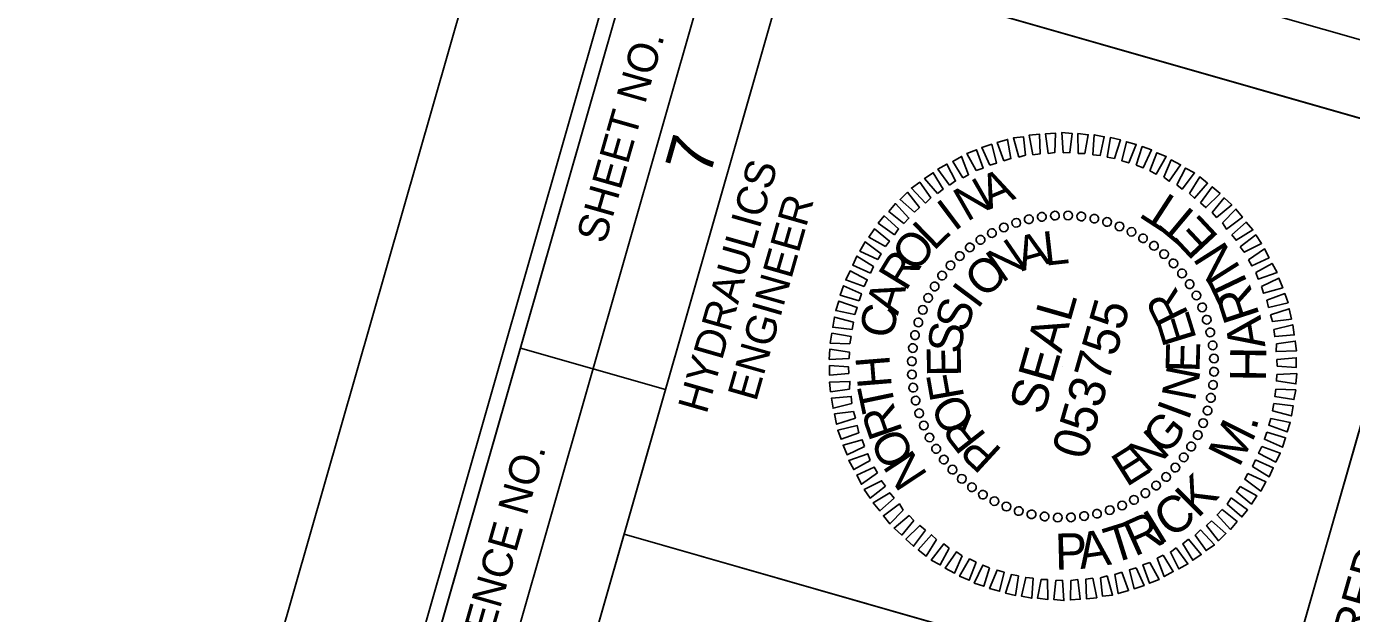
# Model space of a CAD drawing. Extents: x 2096988 to 2098509, y 687711 to 689775.
# Drawn here: x 2097368.1 to 2097587.9, y 689492.9 to 689590.3 of the extents above; entities that cross this region are included whole.
import ezdxf

# ---------------------------------------------------------------- set-up
doc = ezdxf.new("R2010")
doc.units = 0
for name, color, linetype in [('Sheet Data Field CELL', 7, 'Continuous'), ('Sheet PE Seal Cell', 7, 'Continuous'), ('Sheet Plot Border Inside CELL', 7, 'Continuous'), ('Sheet Plot Border Outside CELL', 7, 'Continuous'), ('Sheet Profile CELL', 7, 'Continuous'), ('Sheet Sticker Exception Certification CELL', 7, 'Continuous')]:
    doc.layers.add(name, color=color, linetype=linetype)

msp = doc.modelspace()

# ---------------------------------------------------------------- linework, layer by layer
at = {"layer": 'Sheet PE Seal Cell'}
for p, q in [((2097532.21, 689557.77), (2097532.21, 689557.77)), ((2097534.36, 689558.35), (2097534.36, 689558.35)), ((2097536.51, 689558.78), (2097536.51, 689558.78)), ((2097538.65, 689558.99), (2097538.65, 689558.99)), ((2097540.83, 689558.99), (2097540.83, 689558.99)), ((2097543.06, 689558.77), (2097543.06, 689558.77)), ((2097545.21, 689558.47), (2097545.21, 689558.47)), ((2097547.34, 689557.91), (2097547.34, 689557.91)), ((2097549.41, 689557.16), (2097549.41, 689557.16)), ((2097526.32, 689554.98), (2097526.32, 689554.98)), ((2097528.19, 689556.06), (2097528.19, 689556.06)), ((2097530.19, 689557.05), (2097530.19, 689557.05)), ((2097551.38, 689556.23), (2097551.38, 689556.23)), ((2097553.28, 689555.22), (2097553.28, 689555.22)), ((2097524.54, 689553.67), (2097524.54, 689553.67)), ((2097555.1, 689553.97), (2097555.1, 689553.97)), ((2097521.34, 689550.69), (2097521.34, 689550.69)), ((2097522.84, 689552.29), (2097522.84, 689552.29)), ((2097556.78, 689552.56), (2097556.78, 689552.56)), ((2097558.38, 689551.06), (2097558.38, 689551.06)), ((2097519.93, 689549.01), (2097519.93, 689549.01)), ((2097559.76, 689549.36), (2097559.76, 689549.36)), ((2097518.68, 689547.19), (2097518.68, 689547.19)), ((2097561.07, 689547.58), (2097561.07, 689547.58)), ((2097517.67, 689545.29), (2097517.67, 689545.29)), ((2097562.15, 689545.71), (2097562.15, 689545.71)), ((2097516.74, 689543.32), (2097516.74, 689543.32)), ((2097563.14, 689543.71), (2097563.14, 689543.71)), ((2097563.86, 689541.69), (2097563.86, 689541.69)), ((2097515.99, 689541.25), (2097515.99, 689541.25)), ((2097564.44, 689539.55), (2097564.44, 689539.55)), ((2097515.43, 689539.12), (2097515.43, 689539.12)), ((2097564.87, 689537.4), (2097564.87, 689537.4)), ((2097515.13, 689536.97), (2097515.13, 689536.97)), ((2097565.09, 689535.25), (2097565.09, 689535.25)), ((2097514.91, 689534.74), (2097514.91, 689534.74)), ((2097540, 689533.91), (2097540, 689533.91)), ((2097565.08, 689533.07), (2097565.08, 689533.07)), ((2097514.91, 689532.56), (2097514.91, 689532.56)), ((2097564.86, 689530.84), (2097564.86, 689530.84)), ((2097515.13, 689530.42), (2097515.13, 689530.42)), ((2097564.56, 689528.69), (2097564.56, 689528.69)), ((2097515.55, 689528.27), (2097515.55, 689528.27)), ((2097564, 689526.57), (2097564, 689526.57)), ((2097516.13, 689526.12), (2097516.13, 689526.12)), ((2097516.85, 689524.1), (2097516.85, 689524.1)), ((2097563.25, 689524.49), (2097563.25, 689524.49)), ((2097517.84, 689522.1), (2097517.84, 689522.1)), ((2097562.33, 689522.52), (2097562.33, 689522.52)), ((2097518.92, 689520.23), (2097518.92, 689520.23)), ((2097561.31, 689520.63), (2097561.31, 689520.63)), ((2097520.23, 689518.45), (2097520.23, 689518.45)), ((2097560.06, 689518.8), (2097560.06, 689518.8)), ((2097521.62, 689516.75), (2097521.62, 689516.75)), ((2097557.15, 689515.52), (2097557.15, 689515.52)), ((2097558.65, 689517.12), (2097558.65, 689517.12)), ((2097523.22, 689515.25), (2097523.22, 689515.25)), ((2097524.89, 689513.84), (2097524.89, 689513.84)), ((2097555.45, 689514.14), (2097555.45, 689514.14)), ((2097526.72, 689512.59), (2097526.72, 689512.59)), ((2097528.61, 689511.58), (2097528.61, 689511.58)), ((2097551.81, 689511.75), (2097551.81, 689511.75)), ((2097553.67, 689512.83), (2097553.67, 689512.83)), ((2097530.58, 689510.65), (2097530.58, 689510.65)), ((2097532.66, 689509.9), (2097532.66, 689509.9)), ((2097534.78, 689509.34), (2097534.78, 689509.34)), ((2097536.93, 689509.04), (2097536.93, 689509.04)), ((2097539.16, 689508.82), (2097539.16, 689508.82)), ((2097541.34, 689508.82), (2097541.34, 689508.82)), ((2097543.49, 689509.03), (2097543.49, 689509.03)), ((2097545.64, 689509.46), (2097545.64, 689509.46)), ((2097547.78, 689510.04), (2097547.78, 689510.04)), ((2097549.81, 689510.76), (2097549.81, 689510.76))]:
    msp.add_line(p, q, dxfattribs=at)
for points in [[(2097535.02, 689569.03), (2097534.39, 689572.28), (2097536.11, 689572.46), (2097536.22, 689569.21)], [(2097537.53, 689569.25), (2097537.12, 689572.54), (2097538.76, 689572.64), (2097538.67, 689569.44)], [(2097540.06, 689569.36), (2097539.83, 689572.75), (2097541.5, 689572.59), (2097541.16, 689569.41)], [(2097542.53, 689569.27), (2097542.48, 689572.56), (2097544.2, 689572.38), (2097543.62, 689569.27)], [(2097527.88, 689567.33), (2097526.53, 689570.26), (2097528.19, 689570.78), (2097528.96, 689567.65)], [(2097530.21, 689568.02), (2097529.11, 689571.09), (2097530.81, 689571.59), (2097531.36, 689568.41)], [(2097532.68, 689568.66), (2097531.77, 689571.83), (2097533.44, 689572.03), (2097533.76, 689568.98)], [(2097544.96, 689569.05), (2097545.18, 689572.36), (2097546.86, 689572.04), (2097546.17, 689568.91)], [(2097547.35, 689568.67), (2097547.86, 689571.91), (2097549.52, 689571.54), (2097548.53, 689568.44)], [(2097549.77, 689568.03), (2097550.52, 689571.2), (2097552.15, 689570.73), (2097550.92, 689567.7)], [(2097552.16, 689567.3), (2097553.15, 689570.4), (2097554.71, 689569.85), (2097553.28, 689566.87)], [(2097523.38, 689565.24), (2097521.71, 689567.95), (2097523.19, 689568.78), (2097524.35, 689565.74)], [(2097525.59, 689566.43), (2097524.06, 689569.26), (2097525.65, 689569.89), (2097526.74, 689566.82)], [(2097554.39, 689566.4), (2097555.56, 689569.39), (2097557.14, 689568.73), (2097555.48, 689565.83)], [(2097556.74, 689565.31), (2097557.97, 689568.18), (2097559.51, 689567.38), (2097557.64, 689564.64)], [(2097519.19, 689562.59), (2097517.05, 689565.13), (2097518.47, 689566.07), (2097520.12, 689563.31)], [(2097521.2, 689563.99), (2097519.26, 689566.68), (2097520.75, 689567.5), (2097522.18, 689564.7)], [(2097558.86, 689564.03), (2097560.34, 689566.83), (2097561.83, 689566.04), (2097559.76, 689563.35)], [(2097517.18, 689561.03), (2097514.87, 689563.51), (2097516.24, 689564.47), (2097518.06, 689561.92)], [(2097560.97, 689562.64), (2097562.68, 689565.38), (2097563.99, 689564.33), (2097561.82, 689561.83)], [(2097562.8, 689561.08), (2097564.76, 689563.74), (2097566.05, 689562.59), (2097563.72, 689560.29)], [(2097515.35, 689559.53), (2097512.98, 689561.61), (2097514.21, 689562.82), (2097516.18, 689560.28)], [(2097564.74, 689559.48), (2097566.73, 689561.88), (2097568.01, 689560.73), (2097565.49, 689558.64)], [(2097513.61, 689557.63), (2097511.12, 689559.65), (2097512.21, 689560.94), (2097514.44, 689558.54)], [(2097566.48, 689557.74), (2097568.69, 689560.02), (2097569.76, 689558.67), (2097567.12, 689556.72)], [(2097512.07, 689555.73), (2097509.36, 689557.7), (2097510.33, 689558.89), (2097512.73, 689556.74)], [(2097567.99, 689555.75), (2097570.37, 689557.87), (2097571.5, 689556.56), (2097568.72, 689554.86)], [(2097510.59, 689553.82), (2097507.82, 689555.39), (2097508.72, 689556.74), (2097511.22, 689554.73)], [(2097569.4, 689553.78), (2097571.99, 689555.74), (2097572.94, 689554.33), (2097570.07, 689552.86)], [(2097509.31, 689551.69), (2097506.32, 689553.06), (2097507.17, 689554.59), (2097509.83, 689552.63)], [(2097570.75, 689551.58), (2097573.42, 689553.46), (2097574.18, 689551.94), (2097571.3, 689550.59)], [(2097508.07, 689549.39), (2097505.12, 689550.7), (2097505.82, 689552.22), (2097508.55, 689550.5)], [(2097571.97, 689549.51), (2097574.7, 689551.02), (2097575.52, 689549.53), (2097572.39, 689548.4)], [(2097507.03, 689547.19), (2097503.96, 689548.28), (2097504.7, 689549.78), (2097507.55, 689548.29)], [(2097572.91, 689547.16), (2097575.81, 689548.56), (2097576.45, 689546.98), (2097573.28, 689546.07)], [(2097506.2, 689544.83), (2097503.07, 689545.72), (2097503.58, 689547.3), (2097506.58, 689545.97)], [(2097505.49, 689542.54), (2097502.3, 689543.19), (2097502.8, 689544.76), (2097505.87, 689543.67)], [(2097573.83, 689544.92), (2097576.79, 689546), (2097577.35, 689544.48), (2097574.11, 689543.7)], [(2097505.04, 689540.06), (2097501.81, 689540.41), (2097502.09, 689542.1), (2097505.23, 689541.26)], [(2097574.43, 689542.46), (2097577.53, 689543.49), (2097577.88, 689541.78), (2097574.75, 689541.38)], [(2097574.99, 689540.06), (2097578.12, 689540.83), (2097578.37, 689539.15), (2097575.12, 689538.88)], [(2097504.67, 689537.67), (2097501.37, 689537.78), (2097501.68, 689539.41), (2097504.86, 689538.87)], [(2097575.4, 689537.66), (2097578.54, 689538.11), (2097578.71, 689536.5), (2097575.34, 689536.37)], [(2097504.54, 689535.21), (2097501.22, 689535.07), (2097501.35, 689536.8), (2097504.59, 689536.29)], [(2097575.49, 689535.08), (2097578.69, 689535.36), (2097578.7, 689533.75), (2097575.54, 689533.98)], [(2097504.5, 689532.73), (2097501.3, 689532.45), (2097501.3, 689534.06), (2097504.45, 689533.83)], [(2097504.6, 689530.15), (2097501.45, 689529.7), (2097501.29, 689531.31), (2097504.65, 689531.44)], [(2097575.46, 689532.6), (2097578.77, 689532.74), (2097578.64, 689531.01), (2097575.41, 689531.52)], [(2097505, 689527.75), (2097501.87, 689526.98), (2097501.62, 689528.66), (2097504.87, 689528.93)], [(2097575.32, 689530.14), (2097578.62, 689530.03), (2097578.31, 689528.4), (2097575.14, 689528.94)], [(2097505.56, 689525.35), (2097502.46, 689524.32), (2097502.12, 689526.03), (2097505.25, 689526.43)], [(2097574.95, 689527.75), (2097578.18, 689527.4), (2097577.9, 689525.71), (2097574.77, 689526.55)], [(2097506.16, 689522.89), (2097503.2, 689521.82), (2097502.64, 689523.33), (2097505.88, 689524.11)], [(2097574.5, 689525.28), (2097577.7, 689524.62), (2097577.2, 689523.05), (2097574.13, 689524.14)], [(2097573.8, 689522.98), (2097576.92, 689522.09), (2097576.42, 689520.51), (2097573.42, 689521.84)], [(2097507.08, 689520.65), (2097504.18, 689519.25), (2097503.54, 689520.83), (2097506.71, 689521.74)], [(2097572.96, 689520.62), (2097576.03, 689519.53), (2097575.29, 689518.03), (2097572.44, 689519.52)], [(2097508.02, 689518.3), (2097505.3, 689516.79), (2097504.47, 689518.28), (2097507.61, 689519.41)], [(2097571.92, 689518.42), (2097574.87, 689517.11), (2097574.18, 689515.59), (2097571.44, 689517.31)], [(2097509.25, 689516.24), (2097506.57, 689514.35), (2097505.81, 689515.87), (2097508.7, 689517.22)], [(2097570.69, 689516.12), (2097573.67, 689514.75), (2097572.82, 689513.22), (2097570.16, 689515.18)], [(2097510.59, 689514.03), (2097508, 689512.07), (2097507.05, 689513.48), (2097509.92, 689514.95)], [(2097569.4, 689513.99), (2097572.18, 689512.42), (2097571.27, 689511.07), (2097568.78, 689513.08)], [(2097512.01, 689512.07), (2097509.63, 689509.94), (2097508.5, 689511.25), (2097511.27, 689512.95)], [(2097513.52, 689510.07), (2097511.3, 689507.79), (2097510.23, 689509.14), (2097512.87, 689511.09)], [(2097567.92, 689512.08), (2097570.63, 689510.11), (2097569.67, 689508.93), (2097567.26, 689511.07)], [(2097515.25, 689508.33), (2097513.27, 689505.93), (2097511.98, 689507.08), (2097514.5, 689509.17)], [(2097566.39, 689510.18), (2097568.88, 689508.16), (2097567.78, 689506.87), (2097565.55, 689509.27)], [(2097517.19, 689506.73), (2097515.23, 689504.07), (2097513.95, 689505.22), (2097516.27, 689507.52)], [(2097562.81, 689506.78), (2097565.12, 689504.3), (2097563.75, 689503.34), (2097561.93, 689505.89)], [(2097564.65, 689508.28), (2097567.02, 689506.2), (2097565.79, 689504.99), (2097563.81, 689507.53)], [(2097519.03, 689505.17), (2097517.31, 689502.43), (2097516, 689503.49), (2097518.17, 689505.98)], [(2097521.13, 689503.78), (2097519.65, 689500.98), (2097518.16, 689501.77), (2097520.23, 689504.46)], [(2097560.81, 689505.22), (2097562.94, 689502.69), (2097561.53, 689501.74), (2097559.87, 689504.5)], [(2097523.26, 689502.5), (2097522.02, 689499.63), (2097520.48, 689500.43), (2097522.36, 689503.17)], [(2097556.61, 689502.57), (2097558.28, 689499.86), (2097556.8, 689499.03), (2097555.64, 689502.07)], [(2097558.79, 689503.82), (2097560.73, 689501.13), (2097559.24, 689500.31), (2097557.81, 689503.11)], [(2097525.6, 689501.41), (2097524.43, 689498.42), (2097522.85, 689499.08), (2097524.51, 689501.98)], [(2097527.84, 689500.51), (2097526.85, 689497.42), (2097525.29, 689497.97), (2097526.71, 689500.94)], [(2097530.23, 689499.78), (2097529.48, 689496.61), (2097527.84, 689497.08), (2097529.07, 689500.11)], [(2097552.12, 689500.48), (2097553.46, 689497.55), (2097551.8, 689497.03), (2097551.04, 689500.16)], [(2097554.4, 689501.38), (2097555.93, 689498.55), (2097554.35, 689497.92), (2097553.25, 689500.99)], [(2097532.64, 689499.14), (2097532.13, 689495.9), (2097530.47, 689496.27), (2097531.46, 689499.37)], [(2097535.03, 689498.76), (2097534.81, 689495.45), (2097533.14, 689495.77), (2097533.83, 689498.9)], [(2097537.46, 689498.54), (2097537.51, 689495.25), (2097535.79, 689495.43), (2097536.37, 689498.54)], [(2097539.94, 689498.45), (2097540.16, 689495.06), (2097538.49, 689495.23), (2097538.83, 689498.41)], [(2097542.46, 689498.56), (2097542.88, 689495.27), (2097541.23, 689495.17), (2097541.32, 689498.37)], [(2097544.97, 689498.78), (2097545.6, 689495.53), (2097543.88, 689495.35), (2097543.78, 689498.6)], [(2097547.31, 689499.15), (2097548.23, 689495.98), (2097546.56, 689495.78), (2097546.24, 689498.83)], [(2097549.79, 689499.79), (2097550.88, 689496.72), (2097549.18, 689496.22), (2097548.63, 689499.4)]]:
    msp.add_lwpolyline(points, close=True, dxfattribs=at)
for centre, major_axis in [((2097536.49, 689558.74), (-0.101, 0.713)), ((2097538.67, 689558.95), (-0.038, 0.719)), ((2097540.86, 689558.97), (0.025, 0.72)), ((2097543.04, 689558.8), (0.087, 0.715)), ((2097530.19, 689556.99), (-0.282, 0.663)), ((2097532.24, 689557.75), (-0.223, 0.685)), ((2097534.34, 689558.34), (-0.162, 0.701)), ((2097545.2, 689558.44), (0.149, 0.704)), ((2097547.32, 689557.89), (0.21, 0.689)), ((2097549.38, 689557.16), (0.269, 0.668)), ((2097551.37, 689556.26), (0.327, 0.642)), ((2097526.33, 689554.93), (-0.392, 0.604)), ((2097528.21, 689556.04), (-0.338, 0.636)), ((2097553.28, 689555.18), (0.381, 0.611)), ((2097522.88, 689552.24), (-0.491, 0.526)), ((2097524.55, 689553.66), (-0.444, 0.567)), ((2097555.08, 689553.94), (0.433, 0.575)), ((2097556.77, 689552.55), (0.482, 0.535)), ((2097521.35, 689550.68), (-0.535, 0.482)), ((2097558.33, 689551.02), (0.526, 0.491)), ((2097519.96, 689548.99), (-0.575, 0.433)), ((2097559.75, 689549.36), (0.567, 0.444)), ((2097561.02, 689547.57), (0.604, 0.392)), ((2097517.64, 689545.28), (-0.642, 0.327)), ((2097518.72, 689547.19), (-0.611, 0.381)), ((2097562.14, 689545.69), (0.636, 0.338)), ((2097516.74, 689543.29), (-0.668, 0.269)), ((2097563.08, 689543.72), (0.663, 0.282)), ((2097516.01, 689541.23), (-0.689, 0.21)), ((2097563.85, 689541.67), (0.685, 0.223)), ((2097515.46, 689539.11), (-0.704, 0.149)), ((2097564.43, 689539.56), (0.701, 0.162)), ((2097515.1, 689536.95), (-0.715, 0.087)), ((2097564.83, 689537.41), (0.713, 0.101)), ((2097514.93, 689534.77), (-0.72, 0.025)), ((2097565.04, 689535.23), (0.719, 0.038)), ((2097514.95, 689532.58), (-0.719, -0.038)), ((2097565.06, 689533.04), (0.72, -0.025)), ((2097515.16, 689530.4), (-0.713, -0.101)), ((2097564.89, 689530.86), (0.715, -0.087)), ((2097515.56, 689528.25), (-0.701, -0.162)), ((2097564.53, 689528.7), (0.704, -0.149)), ((2097516.15, 689526.14), (-0.685, -0.223)), ((2097563.98, 689526.58), (0.689, -0.21)), ((2097516.91, 689524.1), (-0.663, -0.282)), ((2097563.25, 689524.52), (0.668, -0.269)), ((2097517.86, 689522.12), (-0.636, -0.338)), ((2097562.35, 689522.53), (0.642, -0.327)), ((2097518.97, 689520.24), (-0.604, -0.392)), ((2097561.27, 689520.62), (0.611, -0.381)), ((2097520.24, 689518.46), (-0.567, -0.444)), ((2097521.66, 689516.79), (-0.526, -0.491)), ((2097558.64, 689517.13), (0.535, -0.482)), ((2097560.03, 689518.82), (0.575, -0.433)), ((2097523.22, 689515.26), (-0.482, -0.535)), ((2097557.11, 689515.57), (0.491, -0.526)), ((2097524.91, 689513.87), (-0.433, -0.575)), ((2097526.72, 689512.63), (-0.381, -0.611)), ((2097553.67, 689512.88), (0.392, -0.604)), ((2097555.45, 689514.15), (0.444, -0.567)), ((2097528.62, 689511.55), (-0.327, -0.642)), ((2097530.61, 689510.65), (-0.269, -0.668)), ((2097549.81, 689510.82), (0.282, -0.663)), ((2097551.78, 689511.77), (0.338, -0.636)), ((2097532.67, 689509.92), (-0.21, -0.689)), ((2097534.79, 689509.37), (-0.149, -0.704)), ((2097536.95, 689509.01), (-0.087, -0.715)), ((2097539.13, 689508.84), (-0.025, -0.72)), ((2097541.32, 689508.86), (0.038, -0.719)), ((2097543.5, 689509.07), (0.101, -0.713)), ((2097545.65, 689509.47), (0.162, -0.701)), ((2097547.76, 689510.06), (0.223, -0.685))]:
    msp.add_ellipse(centre, major_axis=major_axis, ratio=0.999708, dxfattribs=at)
at = {"layer": 'Sheet Plot Border Inside CELL'}
msp.add_lwpolyline([(2098027.36, 687729.29), (2098485.98, 689331.44), (2097471.62, 689621.81), (2097013, 688019.66)], close=True, dxfattribs=at)
at = {"layer": 'Sheet Plot Border Outside CELL'}
msp.add_lwpolyline([(2098045.36, 687710.62), (2098508.8, 689329.59), (2097451.28, 689632.31), (2096987.84, 688013.34)], close=True, dxfattribs=at)
at = {"layer": 'Sheet Profile CELL'}
for p, q in [((2097427.65, 689413.31), (2097482.7, 689605.64)), ((2097450.04, 689536.97), (2097474.08, 689530.09)), ((2097467.2, 689506.06), (2097575.31, 689475.11))]:
    msp.add_line(p, q, dxfattribs=at)
for points in [[(2097470.64, 689609.09), (2097057.83, 688167.01), (2098067.29, 687878.05), (2098480.09, 689320.13)], [(2097415.58, 689416.76), (2097470.64, 689609.09), (2097494.72, 689602.2), (2097439.66, 689409.87)], [(2097467.2, 689506.06), (2097494.72, 689602.2), (2097602.87, 689571.24), (2097575.35, 689475.1)], [(2097439.66, 689409.87), (2097467.2, 689506.06), (2097575.35, 689475.1), (2097547.82, 689378.91)]]:
    msp.add_lwpolyline(points, close=True, dxfattribs=at)
at = {"layer": 'Sheet Sticker Exception Certification CELL'}
msp.add_line((2097547.82, 689378.91), (2097602.87, 689571.22), dxfattribs=at)

# ---------------------------------------------------------------- texts
at = {"layer": 'Sheet Data Field CELL'}
msp.add_text('7', height=7.75, rotation=74.0259, dxfattribs=at).set_placement((2097481.36, 689565.19))
at = {"layer": 'Sheet PE Seal Cell'}
for s, height, rotation, p in [('A', 5.64, 22.643, (2097527.72, 689559.89)), ('N', 5.64, 29.8448, (2097524.07, 689557.86)), ('I', 5.64, 37.046, (2097521.99, 689556.22)), ('T', 6, 146.9816, (2097560.11, 689561.02)), ('T', 6, 140.1814, (2097563.18, 689558.45)), ('L', 5.64, 44.2468, (2097518.57, 689552.99)), ('E', 6, 133.072, (2097566.04, 689555.39)), ('O', 5.64, 51.4471, (2097515.58, 689549.27)), ('N', 5.64, 34.5025, (2097529.89, 689547.67)), ('A', 5.64, 15.7862, (2097533.18, 689549.69)), ('L', 5.64, 6.4267, (2097537.03, 689550.62)), ('R', 5.64, 58.647, (2097513.94, 689546.25)), ('N', 6, 122.3462, (2097569.59, 689550.17)), ('O', 5.64, 43.8594, (2097527.05, 689545)), ('T', 6, 115.546, (2097571.3, 689546.55)), ('A', 5.64, 73.0462, (2097512.59, 689542.27)), ('I', 5.64, 53.2155, (2097525.83, 689543.27)), ('R', 5.64, 116.5073, (2097560.94, 689542.58)), ('R', 6, 108.0657, (2097572.68, 689542.37)), ('C', 5.64, 80.2458, (2097511.79, 689538.39)), ('S', 5.64, 71.9263, (2097523.97, 689539.33)), ('SEAL', 5.998, 74.0259, (2097536.76, 689525.68)), ('053755', 5.998, 74.0259, (2097543.83, 689518.21)), ('E', 5.64, 107.15, (2097562.22, 689538.52)), ('A', 6, 99.2254, (2097573.6, 689537.24)), ('S', 5.64, 81.2815, (2097523.03, 689535.85)), ('E', 5.64, 88.4377, (2097562.64, 689532.88)), ('H', 5.64, 94.6454, (2097511.62, 689530.53)), ('E', 5.64, 90.637, (2097523.09, 689532.24)), ('H', 6, 89.2414, (2097573.67, 689531.37)), ('N', 5.64, 79.0823, (2097561.85, 689527.96)), ('F', 5.64, 99.9929, (2097523.65, 689528.76)), ('T', 5.64, 101.8457, (2097512.31, 689526.95)), ('O', 5.64, 118.7071, (2097525.58, 689524.77)), ('R', 5.64, 109.0464, (2097513.49, 689523.08)), ('R', 5.64, 128.0655, (2097527.45, 689522.41)), ('I', 5.64, 69.7271, (2097560.79, 689524.78)), ('G', 5.64, 51.0161, (2097557.16, 689519.01)), ('M', 6, 63.4778, (2097569.22, 689516.99)), ('.', 6, 75.0073, (2097572.01, 689523.17)), ('O', 5.64, 116.2476, (2097515.52, 689518.91)), ('N', 5.64, 41.6598, (2097553.95, 689515.97)), ('N', 5.64, 123.4494, (2097517.68, 689515.9)), ('P', 5.64, 137.4248, (2097530.09, 689520)), ('E', 5.64, 32.3028, (2097550.53, 689513.83)), ('K', 6, 44.9935, (2097562.34, 689508.59)), ('C', 6, 35.4114, (2097557.82, 689505.23)), ('R', 6, 24.1291, (2097551.86, 689502.29)), ('I', 6, 31.6094, (2097555.88, 689504.11)), ('A', 6, 8.4886, (2097542.9, 689500.27)), ('T', 6, 17.3289, (2097548.04, 689501.11)), ('P', 6, 1.3793, (2097538.72, 689500.16))]:
    msp.add_text(s, height=height, rotation=rotation, dxfattribs=at).set_placement(p)
at = {"layer": 'Sheet Profile CELL'}
for s, height, p in [('SHEET NO.', 5, (2097464.03, 689554.1)), ('HYDRAULICS', 5, (2097480.87, 689525.87)), ('ENGINEER', 5, (2097489.1, 689527.94)), ('PROJECT REFERENCE NO.', 5.0001, (2097430.05, 689435.73))]:
    msp.add_text(s, height=height, rotation=74.0259, dxfattribs=at).set_placement(p)
at = {"layer": 'Sheet Sticker Exception Certification CELL'}
for s, p in [('UNLESS ALL SIGNATURES COMPLETED', (2097570.63, 689389.02)), ('DOCUMENT NOT CONSIDERED FINAL', (2097563.57, 689396.32))]:
    msp.add_text(s, height=5.5, rotation=74.0259, dxfattribs=at).set_placement(p)

doc.saveas('drawing.dxf')
